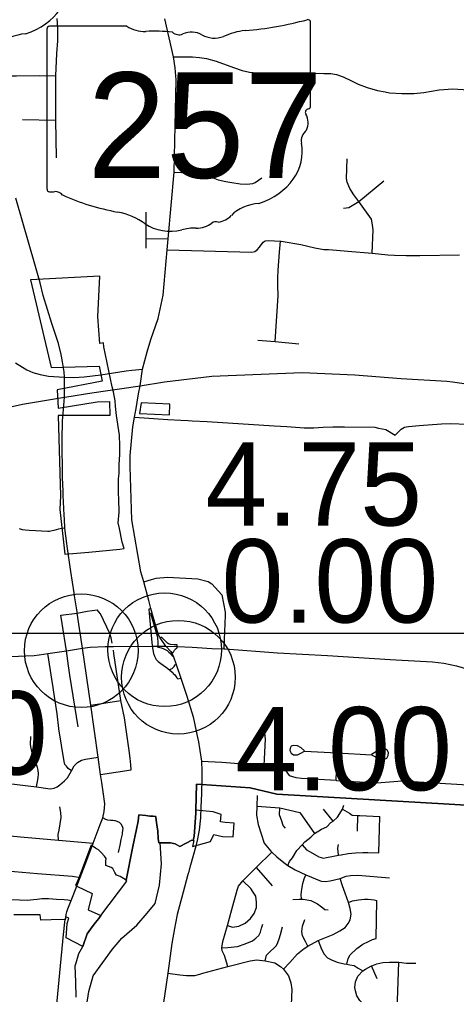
# Model space of a CAD drawing. Extents: x 1729596 to 1934326, y 644115 to 911751.
# Drawn here: x 1795955 to 1801727, y 760728 to 773601 of the extents above; entities that cross this region are included whole.
import ezdxf

# ---------------------------------------------------------------- set-up
doc = ezdxf.new("R2010")
doc.units = 0
for name, color, linetype in [('Default', 7, 'Continuous'), ('GM_X_City_Street', 7, 'Continuous'), ('GM_X_Corporation', 7, 'Continuous'), ('GM_X_County_Road', 7, 'Continuous'), ('GM_X_Interchange_Ramps', 7, 'Continuous'), ('GM_X_Interstate_Route', 7, 'Continuous'), ('GM_X_State_Route', 7, 'Continuous'), ('GM_X_State_Shield', 7, 'Continuous'), ('GM_X_Township', 7, 'Continuous'), ('GM_X_US_Route', 7, 'Continuous'), ('SC_Scratch1', 7, 'Continuous')]:
    doc.layers.add(name, color=color, linetype=linetype)

msp = doc.modelspace()

# ---------------------------------------------------------------- linework, layer by layer
at = {"layer": 'Default'}
for centre in [(1797873, 765280), (1797873, 765280), (1796771, 765267), (1798054, 764917)]:
    msp.add_circle(centre, 750, dxfattribs=at)
at = {"layer": 'GM_X_City_Street'}
for points in [[(1796449, 773613), (1796456, 773496), (1796458, 773320), (1796444, 773152)], [(1796444, 773152), (1796429, 772857), (1796429, 772273), (1796440, 771773)], [(1797988, 773106), (1798240, 773106), (1798334, 773098), (1798427, 773084), (1798551, 773050), (1798780, 772969), (1798894, 772927), (1798995, 772906), (1799091, 772898), (1799975, 772889), (1800066, 772886), (1800142, 772874), (1800230, 772844), (1800351, 772786), (1800430, 772749), (1800549, 772702), (1800684, 772663), (1800785, 772644), (1800841, 772633), (1801003, 772622), (1801065, 772623)], [(1795483, 772817), (1795583, 772849), (1795668, 772859), (1795914, 772857), (1796218, 772860), (1796429, 772857)], [(1801065, 772623), (1801163, 772625), (1801294, 772639), (1801500, 772672), (1801677, 772685), (1801881, 772671), (1802058, 772631), (1802221, 772564), (1802417, 772452), (1802750, 772181), (1802908, 772052), (1802992, 772000), (1803043, 771979), (1803126, 771960), (1803319, 771948)], [(1795994, 772279), (1796429, 772273)], [(1800611, 770514), (1800625, 770825), (1800614, 770917), (1800606, 770963), (1800436, 771196), (1800371, 771285), (1800320, 771371), (1800283, 771452), (1800276, 771500), (1800285, 771760)], [(1797996, 771587), (1798304, 771573), (1798374, 771568), (1798439, 771537), (1798511, 771510), (1798578, 771485), (1798680, 771462), (1798758, 771449), (1798868, 771430), (1798959, 771427), (1799038, 771436), (1799068, 771447), (1799156, 771510)], [(1800436, 771196), (1800765, 771470)], [(1800235, 771108), (1800307, 771117), (1800436, 771196)], [(1797627, 770584), (1797628, 770710), (1797629, 771055)], [(1797628, 770710), (1797918, 770704)], [(1797905, 770559), (1799022, 770530), (1799064, 770538), (1799094, 770562), (1799126, 770593), (1799173, 770659), (1799200, 770678), (1799242, 770682), (1799403, 770676), (1799411, 770676), (1799673, 770632), (1799854, 770588), (1799974, 770563), (1800038, 770564), (1800143, 770554), (1800293, 770542), (1800611, 770514), (1800822, 770496), (1800908, 770489), (1801060, 770485), (1801244, 770484), (1801768, 770492)], [(1799330, 769348), (1799372, 769953), (1799368, 770087), (1799365, 770184), (1799370, 770292), (1799387, 770528), (1799403, 770676)], [(1799105, 769369), (1799330, 769348), (1799645, 769319)], [(1795901, 769069), (1795996, 769010), (1796054, 768976), (1796133, 768942), (1796228, 768913), (1796340, 768892), (1796548, 768877)], [(1796548, 768877), (1796675, 768876), (1796810, 768884), (1797028, 768911), (1797364, 768961)], [(1797364, 768961), (1797439, 768973), (1797581, 768985)], [(1797475, 768350), (1797915, 768321)], [(1797915, 768321), (1798085, 768313), (1798183, 768307)], [(1798183, 768307), (1798237, 768304), (1798432, 768292), (1799320, 768238), (1799487, 768227), (1799716, 768212), (1799736, 768212)], [(1799736, 768212), (1799843, 768208), (1799966, 768217), (1800093, 768224), (1800248, 768223), (1800650, 768217), (1800695, 768207), (1800792, 768187), (1800917, 768113), (1800996, 768194), (1801041, 768219), (1801091, 768229), (1801232, 768240), (1801528, 768262), (1801649, 768269), (1802546, 768230), (1802622, 768207), (1802680, 768153), (1802713, 768084)], [(1796555, 766885), (1796518, 766879), (1796493, 766876), (1796471, 766872), (1796409, 766853), (1796370, 766845), (1796348, 766843), (1796328, 766843), (1796085, 766855), (1796029, 766859), (1795996, 766864), (1795955, 766878)], [(1797598, 766178), (1797698, 766208), (1797762, 766227), (1797910, 766240), (1798309, 766215), (1798448, 766179), (1798495, 766150), (1798627, 766003), (1798673, 765774), (1798672, 765731), (1798658, 765414), (1798653, 765292)], [(1796501, 765736), (1796717, 765765), (1796850, 765789), (1796917, 765796), (1796979, 765809)], [(1797179, 765368), (1797168, 765438), (1797149, 765496), (1797025, 765754), (1796979, 765809)], [(1796622, 764946), (1796603, 765069), (1796577, 765266), (1796518, 765628), (1796501, 765736)], [(1797043, 763527), (1797027, 763634), (1796995, 763860), (1796898, 764550), (1796787, 765300)], [(1797429, 763696), (1797427, 763759), (1797417, 763850), (1797402, 763948), (1797341, 764382), (1797294, 764609), (1797201, 765231), (1797197, 765274)], [(1796393, 764833), (1796366, 765005), (1796331, 765229)], [(1796730, 764262), (1796622, 764946)], [(1796477, 764238), (1796477, 764242), (1796454, 764432), (1796411, 764722), (1796397, 764813), (1796393, 764833)], [(1796898, 764550), (1797294, 764609)], [(1796643, 763682), (1796599, 763714), (1796574, 763741), (1796556, 763767), (1796545, 763803), (1796477, 764238)], [(1796180, 763468), (1796200, 763588), (1796205, 763642), (1796202, 763689), (1796191, 763725), (1796131, 763914), (1796118, 763938), (1796108, 763979), (1796102, 764027), (1796104, 764134)], [(1799187, 763750), (1799204, 764101), (1799196, 764181)], [(1799721, 763945), (1799674, 763986), (1799628, 764010), (1799580, 764017), (1799544, 764007), (1799528, 763982), (1799525, 763950), (1799543, 763915), (1799573, 763891), (1799625, 763892), (1799671, 763916), (1799719, 763939), (1800149, 763918), (1800604, 763894), (1800711, 763841), (1800769, 763830), (1800806, 763850), (1800824, 763882), (1800828, 763922), (1800813, 763956), (1800785, 763972), (1800745, 763967), (1800691, 763949), (1800604, 763896)], [(1795264, 763582), (1796068, 763485), (1796180, 763468), (1796328, 763447), (1796363, 763445), (1796415, 763452), (1796453, 763470), (1796486, 763497), (1796551, 763550), (1796590, 763591), (1796643, 763682), (1796677, 763749), (1796722, 763792), (1796773, 763823), (1796825, 763837), (1796995, 763860)], [(1800138, 763556), (1800149, 763918)], [(1798361, 763811), (1798627, 763794), (1798910, 763775), (1799187, 763750), (1799393, 763707), (1799473, 763682), (1799519, 763619), (1799605, 763594), (1799681, 763585), (1800138, 763556), (1800142, 763555), (1800675, 763521), (1801008, 763551), (1801581, 763516), (1802396, 763466), (1802931, 763434), (1802973, 763432)], [(1797027, 763634), (1797429, 763696)], [(1796943, 762762), (1797020, 762971), (1797054, 763059), (1797074, 763146), (1797080, 763194), (1797081, 763246), (1797062, 763405), (1797053, 763464), (1797043, 763527)], [(1799096, 763357), (1799088, 763214), (1799085, 763098), (1799106, 762974), (1799188, 762726), (1799273, 762620), (1799287, 762607), (1799356, 762545), (1799447, 762470), (1799498, 762433)], [(1796472, 762768), (1796467, 762842), (1796478, 762899), (1796505, 763067), (1796502, 763130), (1796486, 763206)], [(1799088, 763214), (1799394, 763195), (1799659, 763131), (1799851, 762855)], [(1799498, 762433), (1799523, 762483), (1799559, 762533), (1799619, 762630), (1799687, 762705), (1799724, 762745), (1799805, 762804), (1799851, 762855), (1799946, 762911), (1800016, 762940), (1800069, 762999), (1800097, 763018), (1800154, 763068), (1800187, 763116), (1800220, 763174), (1800238, 763228)], [(1799469, 762923), (1799437, 762961), (1799418, 763015), (1799389, 763101), (1799394, 763195)], [(1800097, 763018), (1799970, 763174)], [(1800220, 763174), (1800315, 763122), (1800350, 763094), (1800422, 763092), (1800452, 763091), (1800716, 763077)], [(1800420, 762883), (1800422, 763092)], [(1800700, 762599), (1800716, 763077)], [(1797314, 762847), (1797316, 762857), (1797322, 762899), (1797323, 762922), (1797314, 762947), (1797298, 762978), (1797275, 763001), (1797247, 763014), (1797225, 763021), (1797210, 763023), (1797187, 763024), (1797158, 763026), (1797124, 763030), (1797096, 763041), (1797054, 763059)], [(1795273, 762874), (1795970, 762810), (1796472, 762768), (1796929, 762725)], [(1797283, 762700), (1797297, 762774), (1797314, 762847)], [(1796924, 762713), (1796929, 762725), (1796943, 762762)], [(1797263, 762602), (1797283, 762700)], [(1799687, 762705), (1799747, 762637), (1799794, 762610), (1799907, 762546), (1799939, 762538), (1799969, 762530), (1800011, 762537), (1800079, 762550), (1800170, 762567), (1800202, 762573), (1800294, 762588), (1800394, 762597), (1800488, 762603), (1800558, 762605), (1800700, 762599)], [(1800170, 762567), (1800159, 762660), (1800167, 762710)], [(1798705, 761096), (1798661, 761244), (1798634, 761304), (1798628, 761344), (1798640, 761430), (1798702, 761640), (1798772, 761899), (1798830, 762105), (1798849, 762157), (1798904, 762230), (1799082, 762406), (1799287, 762607)], [(1799498, 762433), (1799595, 762374), (1799739, 762307), (1799939, 762223), (1799991, 762219), (1800059, 762228), (1800190, 762261), (1800268, 762290), (1800328, 762299), (1800424, 762302), (1800844, 762270)], [(1795173, 762405), (1795682, 762369), (1796194, 762325), (1796655, 762290), (1796758, 762273)], [(1799082, 762406), (1799291, 762163)], [(1799679, 761987), (1799677, 762048), (1799684, 762118), (1799699, 762192), (1799714, 762256), (1799739, 762307)], [(1796570, 761777), (1796572, 761786), (1796581, 761819), (1796594, 761860), (1796637, 761969), (1796714, 762158), (1796719, 762171)], [(1798702, 761640), (1798770, 761619), (1798852, 761632), (1798935, 761671), (1799006, 761732), (1799056, 761797), (1799085, 761875), (1799086, 761947), (1799077, 762026), (1799042, 762078), (1799011, 762129), (1798904, 762230)], [(1799442, 761063), (1799524, 761149), (1799625, 761264), (1799716, 761337), (1799763, 761366), (1799902, 761442), (1800100, 761522), (1800185, 761567), (1800256, 761614), (1800296, 761664), (1800321, 761716), (1800334, 761788), (1800323, 761864), (1800302, 761941), (1800255, 762065), (1800221, 762162), (1800190, 762261)], [(1795213, 762012), (1795249, 762013), (1795520, 761998), (1796061, 761976), (1796140, 761982), (1796190, 761987), (1796249, 761994), (1796339, 761994), (1796445, 761988), (1796545, 761984), (1796594, 761977), (1796637, 761969)], [(1799567, 761984), (1799649, 761987), (1799679, 761987), (1799701, 761988), (1799802, 761969), (1799890, 761926), (1799961, 761871), (1799987, 761852), (1800031, 761846)], [(1800279, 761128), (1800296, 761203), (1800322, 761251), (1800411, 761334), (1800489, 761392), (1800565, 761428), (1800619, 761453), (1800664, 761467), (1800673, 761968)], [(1800302, 761941), (1800353, 761964), (1800431, 761977), (1800513, 761985), (1800559, 761985), (1800641, 761978), (1800673, 761968)], [(1798628, 761344), (1798705, 761347), (1798835, 761363), (1798935, 761396), (1799032, 761437), (1799078, 761471), (1799117, 761508), (1799137, 761552), (1799152, 761604), (1799167, 761658)], [(1799763, 761366), (1799731, 761429), (1799694, 761501), (1799683, 761561), (1799692, 761629), (1799725, 761719)], [(1799200, 761175), (1799217, 761247), (1799252, 761284), (1799272, 761302), (1799315, 761342), (1799349, 761377), (1799369, 761413), (1799386, 761463), (1799401, 761519), (1799430, 761623)], [(1799902, 761442), (1799943, 761325), (1799978, 761259), (1800022, 761214), (1800076, 761184), (1800150, 761155), (1800245, 761133), (1800279, 761128), (1800317, 761122), (1800375, 761110), (1800429, 761078), (1800489, 761043)], [(1798336, 760998), (1798376, 761009), (1798705, 761096), (1799001, 761175), (1799091, 761186), (1799200, 761175), (1799326, 761146), (1799402, 761099), (1799442, 761063), (1799507, 760976), (1799540, 760882), (1799551, 760795), (1799543, 760593), (1799515, 760423), (1799520, 760308), (1799532, 760227), (1799555, 760162), (1799571, 760132)], [(1800489, 761043), (1800525, 761063), (1800563, 761087), (1800604, 761106), (1800609, 761109), (1800673, 761134), (1800752, 761150), (1800840, 761157), (1800956, 761157), (1800965, 761156), (1801068, 761144), (1801188, 761143)], [(1800941, 760396), (1800965, 761156)], [(1797914, 761010), (1798072, 760987), (1798072, 760987)], [(1800650, 760331), (1800619, 760405), (1800585, 760486), (1800544, 760538), (1800534, 760551), (1800502, 760594), (1800452, 760651), (1800411, 760711), (1800391, 760777), (1800385, 760823), (1800394, 760894), (1800424, 760970), (1800489, 761043)], [(1800680, 760934), (1800604, 761106)], [(1798072, 760987), (1798159, 760980), (1798178, 760980)], [(1798178, 760980), (1798271, 760980), (1798336, 760998)]]:
    msp.add_lwpolyline(points, dxfattribs=at)
at = {"layer": 'GM_X_Corporation'}
for points in [[(1796099, 770163), (1796374, 769005), (1797006, 769026), (1797045, 768825), (1796452, 768712), (1796465, 768470), (1796979, 768555), (1797142, 768559), (1797150, 768374), (1796465, 768373), (1796499, 767312), (1796490, 767130), (1796555, 766544), (1796870, 766570), (1797279, 766609), (1797338, 766615), (1797312, 766701), (1797277, 766882), (1797259, 766955), (1797271, 767095), (1797270, 767147), (1797268, 767221), (1797269, 767275), (1797264, 767337), (1797264, 767536), (1797272, 767608), (1797272, 767726), (1797279, 767856), (1797281, 767972), (1797274, 768111), (1797235, 768372), (1797225, 768494), (1797217, 768565), (1797195, 768683), (1797178, 768750), (1797069, 769278), (1797065, 769330), (1797015, 769322), (1796989, 769674), (1797017, 770212)], [(1797541, 768401), (1797935, 768382), (1797940, 768524), (1797562, 768542)]]:
    msp.add_lwpolyline(points, close=True, dxfattribs=at)
for points in [[(1802922, 763165), (1799354, 763375), (1799001, 763458), (1798362, 763501), (1798291, 763505), (1798285, 763163), (1798285, 763121), (1798261, 762817), (1798251, 762763), (1798232, 762768), (1798071, 762682), (1798010, 762716), (1797948, 762730), (1797881, 762730), (1797797, 762730), (1797788, 762787), (1797782, 762885), (1797770, 762968), (1797761, 763030), (1797757, 763077), (1797721, 763081), (1797676, 763083), (1797623, 763091), (1797533, 763101), (1797522, 763017), (1797500, 762912), (1797453, 762684), (1797363, 762240), (1797328, 762261), (1797285, 762286), (1797235, 762306), (1797215, 762337), (1797189, 762393), (1797166, 762407), (1797095, 762431), (1797095, 762464), (1797096, 762492), (1797098, 762526), (1797079, 762553), (1797035, 762603), (1796999, 762638), (1796960, 762661), (1796901, 762700), (1796787, 762397), (1796734, 762256), (1796695, 762167), (1796714, 762158), (1796917, 762062), (1796864, 761847), (1797028, 761773), (1797003, 761733), (1796961, 761681), (1796917, 761623), (1796847, 761530), (1796792, 761362), (1796570, 761475), (1796586, 761667), (1796609, 761738), (1796566, 761754), (1796559, 761715), (1796509, 761719), (1796236, 761708), (1796228, 761782), (1795879, 761782)], [(1796705, 760694), (1796699, 760891), (1796690, 761106), (1796705, 761148), (1796741, 761269), (1796792, 761362), (1796847, 761530), (1796917, 761623), (1796961, 761681), (1797003, 761733), (1797028, 761773), (1797374, 762223), (1797363, 762240), (1797453, 762684), (1797500, 762912), (1797522, 763017), (1797533, 763101), (1797623, 763091), (1797676, 763083), (1797721, 763081), (1797757, 763077), (1797761, 763030), (1797770, 762968), (1797782, 762885), (1797788, 762787), (1797797, 762730), (1797881, 762730), (1797948, 762730), (1798010, 762716), (1798071, 762682), (1798232, 762768), (1798251, 762763), (1798259, 762760), (1798240, 762681), (1798478, 762748), (1798523, 762842), (1798636, 762814), (1798776, 762808), (1798789, 762992), (1798672, 762998), (1798612, 763008), (1798618, 763105), (1798514, 763138), (1798285, 763163), (1798291, 763505), (1798362, 763501), (1799001, 763458), (1799354, 763375), (1802922, 763165)]]:
    msp.add_lwpolyline(points, dxfattribs=at)
at = {"layer": 'GM_X_County_Road'}
for points in [[(1796719, 762171), (1796758, 762273), (1796845, 762504), (1796924, 762713)], [(1796357, 759662), (1796357, 759704), (1796433, 760414), (1796537, 761520), (1796555, 761684), (1796559, 761715), (1796561, 761725)], [(1796561, 761725), (1796566, 761754), (1796570, 761777)]]:
    msp.add_lwpolyline(points, dxfattribs=at)
at = {"layer": 'GM_X_Interchange_Ramps'}
for points in [[(1797690, 765825), (1797662, 765817), (1797667, 765762), (1797704, 765375), (1797708, 765334), (1797708, 765328), (1797709, 765326), (1797715, 765278), (1797726, 765231), (1797739, 765194), (1797762, 765153), (1797788, 765123), (1797821, 765097), (1797853, 765075), (1797895, 765045), (1797936, 765016), (1797972, 764984), (1797987, 764968), (1798005, 764947), (1798033, 764911), (1798047, 764895), (1798084, 764907)], [(1797667, 765762), (1797684, 765764), (1797776, 765447), (1797781, 765365), (1797782, 765329)], [(1798039, 765321), (1798038, 765344), (1797996, 765346), (1797951, 765349), (1797937, 765353), (1797924, 765359), (1797910, 765366), (1797829, 765447), (1797813, 765436)], [(1797774, 765328), (1797774, 765318), (1797825, 765307), (1797853, 765296), (1797879, 765284), (1797904, 765268), (1797929, 765250), (1797945, 765234), (1797955, 765223), (1797975, 765197), (1797985, 765201)], [(1797967, 765235), (1797985, 765247), (1797992, 765259), (1798002, 765275), (1798010, 765285), (1798017, 765292), (1798028, 765300), (1798039, 765306), (1798039, 765321)], [(1797936, 765016), (1797948, 765024), (1797960, 765028), (1797971, 765034), (1797980, 765041), (1797991, 765050), (1797997, 765058), (1798010, 765080), (1798024, 765085)]]:
    msp.add_lwpolyline(points, dxfattribs=at)
at = {"layer": 'GM_X_Interstate_Route'}
for points in [[(1797276, 768725), (1797548, 768766), (1797871, 768815), (1798496, 768890), (1799689, 768939), (1800384, 768911), (1800997, 768863), (1801598, 768824), (1801674, 768816), (1802190, 768744), (1802290, 768736), (1802912, 768691), (1803149, 768674), (1803187, 768671), (1803233, 768671)], [(1790996, 765160), (1790996, 765160), (1791136, 765338), (1791293, 765545), (1791424, 765727), (1791563, 765902), (1791639, 765999), (1791765, 766152), (1791885, 766273), (1792103, 766496), (1792406, 766783), (1792528, 766888), (1792835, 767127), (1793142, 767353), (1793389, 767507), (1793661, 767657), (1794496, 768088), (1794857, 768208), (1795120, 768293), (1795338, 768375), (1795996, 768522), (1796550, 768614), (1796639, 768628)], [(1796639, 768628), (1796854, 768661), (1797062, 768692), (1797276, 768725)]]:
    msp.add_lwpolyline(points, dxfattribs=at)
at = {"layer": 'GM_X_State_Route'}
for points in [[(1797529, 768657), (1797548, 768766), (1797581, 768985), (1797643, 769214), (1797690, 769377), (1797786, 769653), (1797853, 769962), (1797905, 770559), (1797918, 770704), (1797996, 771587), (1797996, 771591), (1798023, 772805), (1798010, 772961), (1797988, 773106), (1797874, 773609)], [(1796165, 770339), (1795905, 771243)], [(1796384, 769586), (1796267, 769959), (1796228, 770123), (1796165, 770339)], [(1796513, 769134), (1796505, 769178), (1796470, 769325), (1796410, 769506), (1796384, 769586)], [(1796522, 769083), (1796519, 769102), (1796513, 769134)], [(1796549, 768771), (1796548, 768877), (1796544, 768948), (1796522, 769083)], [(1796550, 768614), (1796549, 768771)], [(1796545, 768561), (1796550, 768614)], [(1797491, 768440), (1797529, 768657)], [(1796535, 768454), (1796545, 768561)], [(1796525, 768293), (1796527, 768361), (1796535, 768454)], [(1797662, 765932), (1797598, 766178), (1797559, 766307), (1797439, 766997), (1797419, 767698), (1797419, 767844), (1797452, 768221), (1797475, 768350), (1797487, 768422), (1797491, 768440)], [(1796530, 767379), (1796523, 767550), (1796519, 768058), (1796525, 768293)], [(1796548, 767003), (1796544, 767058), (1796533, 767319), (1796530, 767379)], [(1796580, 766682), (1796555, 766885), (1796548, 767003)], [(1796682, 765991), (1796676, 766030), (1796635, 766313), (1796584, 766648), (1796580, 766682)], [(1796715, 765779), (1796682, 765991)], [(1797722, 765713), (1797690, 765825), (1797662, 765932)], [(1796787, 765300), (1796717, 765765), (1796715, 765779)], [(1797788, 765489), (1797722, 765713)], [(1797890, 765326), (1797813, 765436), (1797794, 765469), (1797788, 765489)], [(1797890, 765326), (1798039, 765321), (1798235, 765312), (1798302, 765309)], [(1798302, 765309), (1798497, 765298), (1798653, 765292), (1798670, 765290)], [(1798670, 765290), (1799362, 765240), (1800021, 765204), (1800851, 765152), (1801408, 765122), (1801560, 765103), (1801728, 765068), (1801876, 765025), (1801994, 764982), (1802098, 764934), (1802195, 764884), (1802305, 764816), (1802588, 764624), (1802766, 764496)]]:
    msp.add_lwpolyline(points, dxfattribs=at)
at = {"layer": 'GM_X_State_Shield'}
for p, q in [((1797372, 773511), (1796353, 773511)), ((1799799, 772458), (1799799, 773563)), ((1796318, 773474), (1796318, 771361)), ((1799798, 772458), (1799799, 772458))]:
    msp.add_line(p, q, dxfattribs=at)
for centre, major_axis, start_param, end_param in [((1795686, 774094), (923, 0), 5.101752, 6.440018), ((1796358, 773479), (40.3, 0), 1.712693, 3.28349), ((1797615, 773756), (391, 0), 4.042523, 4.731795), ((1798559, 776392), (3691, 0), 4.814394, 5.042369), ((1799760, 773568), (38.7, 0), 6.141152, 7.989035), ((1796075, 773007), (506, 0), 1.647645, 2.488434), ((1797744, 772324), (1404, 0), 1.404758, 1.657858), ((1798063, 773490), (113, 0), 3.836095, 5.185415), ((1798229, 773246), (235, 0), 0.950623, 2.079405), ((1798531, 773581), (282, 0), 4.081561, 5.145723), ((1799030, 772865), (743, 0), 1.699011, 2.107814), ((1799790, 772377), (60, 0), 1.883978, 3.671073), ((1799408, 772237), (360, 0), 5.934695, 6.695948), ((1799757, 772453), (41.5, 0), 5.05454, 6.418171), ((1799938, 771995), (262, 0), 2.387724, 3.262537), ((1798766, 771854), (923, 0), 5.101752, 6.440018), ((1796359, 771357), (40.7, 0), 3.00124, 4.508301), ((1796365, 771573), (310, 0), 4.665946, 4.897461), ((1796428, 771239), (112, 0), 0.519207, 1.627899), ((1797841, 773138), (2665, 0), 4.195997, 4.488961), ((1797047, 770412), (834, 0), 0.823519, 1.323587), ((1799155, 770768), (506, 0), 1.647645, 2.488434), ((1798548, 770866), (79.4, 0), 1.147584, 2.315152), ((1798514, 771156), (298, 0), 4.937069, 5.64225), ((1797949, 771229), (529, 0), 4.026481, 4.996735), ((1798255, 770498), (435, 0), 1.495662, 1.94098), ((1798293, 771071), (282, 0), 4.691044, 5.507374)]:
    msp.add_ellipse(centre, major_axis=major_axis, ratio=0.8, start_param=start_param, end_param=end_param, dxfattribs=at)
at = {"layer": 'GM_X_Township'}
msp.add_lwpolyline([(1796841, 760568), (1796869, 760769), (1796927, 760975), (1797183, 761325), (1797309, 761472), (1797505, 761645), (1797642, 761801), (1797745, 761932), (1797806, 762172), (1797832, 762455), (1797815, 762730), (1797948, 762730), (1798010, 762716), (1798071, 762682), (1798232, 762768), (1798251, 762763), (1798261, 762817), (1798285, 763121), (1798285, 763163), (1798291, 763505), (1798362, 763501), (1799001, 763458), (1799354, 763375), (1802922, 763165)], dxfattribs=at)
at = {"layer": 'GM_X_US_Route'}
for points in [[(1796216, 765215), (1796331, 765229), (1796577, 765266), (1796787, 765300)], [(1796787, 765300), (1796888, 765313), (1797087, 765325), (1797198, 765323), (1797708, 765328), (1797774, 765328), (1797782, 765329), (1797890, 765326)], [(1797890, 765326), (1797952, 765258), (1797967, 765235), (1797985, 765201), (1798024, 765085), (1798084, 764907), (1798165, 764666), (1798247, 764393), (1798311, 764098)], [(1795062, 765181), (1795110, 765181), (1795212, 765184), (1795398, 765186), (1795845, 765192), (1796038, 765198), (1796147, 765206), (1796216, 765215)], [(1798311, 764098), (1798313, 764090), (1798361, 763811), (1798362, 763675), (1798362, 763524)], [(1798361, 763471), (1798359, 763376), (1798352, 763208)], [(1798362, 763524), (1798362, 763501), (1798361, 763471)], [(1798352, 763208), (1798346, 763063), (1798328, 762896), (1798296, 762739)], [(1798283, 762688), (1798246, 762547), (1798214, 762435)], [(1798296, 762739), (1798294, 762729), (1798283, 762688)], [(1798214, 762435), (1798211, 762425), (1798186, 762333)], [(1798186, 762333), (1798184, 762326), (1798176, 762297), (1798116, 762079), (1798039, 761786), (1798017, 761671)], [(1798017, 761671), (1798003, 761602), (1797969, 761401), (1797914, 761010), (1797836, 760475)]]:
    msp.add_lwpolyline(points, dxfattribs=at)
at = {"layer": 'SC_Scratch1'}
msp.add_lwpolyline([(1729596, 899996), (1925846, 899996), (1925846, 765496), (1729596, 765496)], close=True, dxfattribs=at)

# ---------------------------------------------------------------- texts
at = {"layer": 'Default'}
for s, p in [('4.75', (1798410, 766920)), ('0.00', (1798623, 765639)), ('0.00', (1793465, 763632)), ('4.00', (1798804, 763424))]:
    msp.add_text(s, height=1100, dxfattribs=at).set_placement(p)
at = {"layer": 'GM_X_State_Shield'}
msp.add_text('257', height=1392.2, dxfattribs=at).set_placement((1796854, 771510))

doc.saveas('drawing.dxf')
